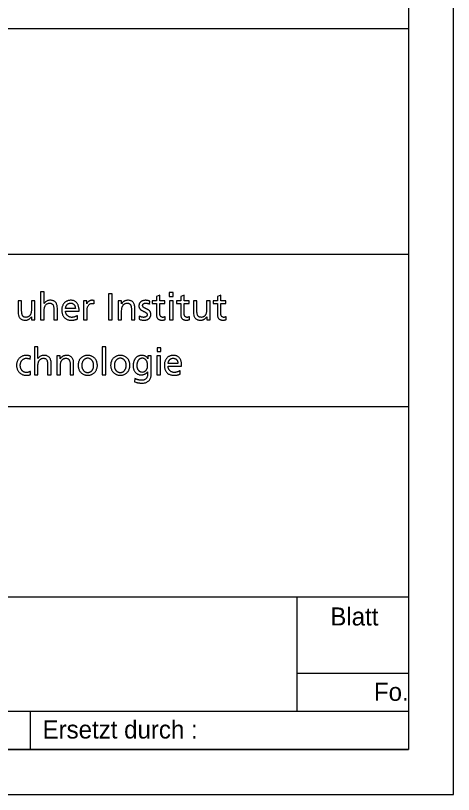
# Model space of a CAD drawing. Extents: x 0 to 841, y 0 to 594.
# Drawn here: x 792.3 to 841, y 0 to 86.5 of the extents above; entities that cross this region are included whole.
import ezdxf

# ---------------------------------------------------------------- set-up
doc = ezdxf.new("R2010")
doc.units = 0
doc.layers.add('90_Plankopf', color=7, linetype='Continuous')

msp = doc.modelspace()

# ---------------------------------------------------------------- linework, layer by layer
at = {"layer": '90_Plankopf'}
for p, q in [((836, 84.99), (658.12, 84.99)), ((836, 84.99), (836, 5)), ((658.12, 59.99), (836, 59.99)), ((658.12, 59.99), (836, 59.99)), ((836, 59.99), (836, 5)), ((801.057, 54.484), (801.057, 54.831)), ((807.232, 54.439), (807.265, 54.778)), ((798.972, 53.96), (797.883, 53.96)), ((797.883, 53.672), (799.385, 53.672)), ((799.224, 52.793), (799.224, 53.18)), ((806.072, 53.118), (806.052, 52.772)), ((808.962, 52.714), (808.962, 53.044)), ((811.666, 52.714), (811.666, 53.044)), ((815.744, 52.714), (815.744, 53.044)), ((793.951, 48.336), (793.984, 48.658)), ((810.373, 47.841), (809.283, 47.841)), ((794.001, 46.623), (793.972, 46.97)), ((809.283, 47.552), (810.785, 47.552)), ((810.624, 46.673), (810.624, 47.061)), ((805.596, 46.174), (805.555, 45.815)), ((752.001, 43.07), (836, 43.07)), ((752.001, 21.92), (836, 21.92)), ((823.647, 9.23), (823.647, 21.92)), ((823.647, 13.46), (836, 13.46)), ((752.001, 9.23), (836, 9.23)), ((794.001, 5), (794.001, 9.23)), ((836, 5), (658.12, 5)), ((669.8, 5), (836, 5)), ((669.8, 5), (836, 5))]:
    msp.add_line(p, q, dxfattribs=at)
for points in [[(0, 0), (841, 0), (841, 594), (0, 594)], [(25, 589), (836, 589), (836, 5), (25, 5)]]:
    msp.add_lwpolyline(points, close=True, dxfattribs=at)
for points in [[(795.509, 54.509), (795.501, 54.509), (795.501, 55.801), (795.113, 55.801), (795.113, 52.706), (795.501, 52.706), (795.501, 53.68)], [(802.646, 52.706), (803.059, 52.706), (803.059, 55.586), (802.646, 55.586), (802.646, 52.706)], [(808.371, 53.345), (808.371, 54.497), (808.929, 54.497), (808.929, 54.81), (808.371, 54.81), (808.371, 55.421), (807.984, 55.297), (807.984, 54.81), (807.509, 54.81), (807.509, 54.497), (807.984, 54.497), (807.984, 53.267)], [(809.853, 55.281), (809.853, 55.718), (809.416, 55.718), (809.416, 55.281), (809.853, 55.281)], [(811.075, 53.345), (811.075, 54.497), (811.633, 54.497), (811.633, 54.81), (811.075, 54.81), (811.075, 55.421), (810.688, 55.297), (810.688, 54.81), (810.213, 54.81), (810.213, 54.497), (810.688, 54.497), (810.688, 53.267)], [(815.154, 53.345), (815.154, 54.497), (815.711, 54.497), (815.711, 54.81), (815.154, 54.81), (815.154, 55.421), (814.766, 55.297), (814.766, 54.81), (814.291, 54.81), (814.291, 54.497), (814.766, 54.497), (814.766, 53.267)], [(793.004, 53.721), (793.004, 54.81), (792.616, 54.81), (792.616, 53.56)], [(794.093, 53.04), (794.102, 53.04), (794.102, 52.706), (794.477, 52.706), (794.477, 54.81), (794.089, 54.81), (794.089, 53.836)], [(800.252, 54.484), (800.244, 54.484), (800.244, 54.81), (799.881, 54.81), (799.881, 52.706), (800.269, 52.706), (800.269, 53.663)], [(804.116, 54.476), (804.108, 54.476), (804.108, 54.81), (803.732, 54.81), (803.732, 52.706), (804.12, 52.706), (804.12, 53.68)], [(809.441, 54.81), (809.441, 52.706), (809.829, 52.706), (809.829, 54.81), (809.441, 54.81)], [(812.483, 53.721), (812.483, 54.81), (812.095, 54.81), (812.095, 53.56)], [(813.573, 53.04), (813.581, 53.04), (813.581, 52.706), (813.956, 52.706), (813.956, 54.81), (813.568, 54.81), (813.568, 53.836)], [(796.587, 53.795), (796.587, 52.706), (796.974, 52.706), (796.974, 53.956)], [(805.205, 53.795), (805.205, 52.706), (805.593, 52.706), (805.593, 53.956)], [(794.818, 48.39), (794.81, 48.39), (794.81, 49.681), (794.422, 49.681), (794.422, 46.586), (794.81, 46.586), (794.81, 47.56)], [(801.963, 46.586), (802.351, 46.586), (802.351, 49.681), (801.963, 49.681), (801.963, 46.586)], [(808.493, 49.161), (808.493, 49.599), (808.056, 49.599), (808.056, 49.161), (808.493, 49.161)], [(797.303, 48.357), (797.295, 48.357), (797.295, 48.691), (796.919, 48.691), (796.919, 46.586), (797.307, 46.586), (797.307, 47.56)], [(807.395, 46.677), (807.395, 48.691), (807.036, 48.691), (807.036, 48.378), (807.028, 48.378)], [(808.031, 48.691), (808.031, 46.586), (808.419, 46.586), (808.419, 48.691), (808.031, 48.691)], [(795.895, 47.676), (795.895, 46.586), (796.283, 46.586), (796.283, 47.837)], [(798.393, 47.676), (798.393, 46.586), (798.78, 46.586), (798.78, 47.837)], [(806.999, 46.912), (807.007, 46.912), (807.007, 46.706)]]:
    msp.add_lwpolyline(points, dxfattribs=at)
for points in [[(795.501, 53.68), (795.501, 53.808), (795.514, 53.925), (795.539, 54.031), (795.565, 54.137), (795.603, 54.228), (795.655, 54.305), (795.708, 54.382), (795.774, 54.441), (795.855, 54.483), (795.935, 54.525), (796.031, 54.546), (796.141, 54.546), (796.253, 54.54), (796.342, 54.509), (796.407, 54.451), (796.473, 54.395), (796.519, 54.312), (796.546, 54.204), (796.574, 54.095), (796.587, 53.959), (796.587, 53.795)], [(796.974, 53.956), (796.975, 54.145), (796.947, 54.307), (796.891, 54.442), (796.836, 54.577), (796.749, 54.68), (796.633, 54.751), (796.516, 54.823), (796.368, 54.859), (796.186, 54.86), (796.038, 54.859), (795.907, 54.829), (795.791, 54.768), (795.675, 54.708), (795.581, 54.621), (795.509, 54.509)], [(799.385, 53.672), (799.386, 53.841), (799.37, 53.999), (799.339, 54.143), (799.307, 54.287), (799.256, 54.412), (799.184, 54.519), (799.112, 54.627), (799.017, 54.71), (798.898, 54.769), (798.779, 54.829), (798.631, 54.859), (798.457, 54.86), (798.307, 54.859), (798.173, 54.833), (798.051, 54.782), (797.931, 54.729), (797.827, 54.656), (797.741, 54.561), (797.654, 54.467), (797.587, 54.355), (797.541, 54.224), (797.494, 54.095), (797.471, 53.952), (797.47, 53.795), (797.47, 53.623), (797.492, 53.468), (797.536, 53.328), (797.579, 53.188), (797.646, 53.069), (797.735, 52.969), (797.825, 52.869), (797.937, 52.792), (798.074, 52.738), (798.212, 52.684), (798.373, 52.657), (798.56, 52.656), (798.675, 52.657), (798.772, 52.665), (798.853, 52.68), (798.934, 52.695), (799.004, 52.713), (799.063, 52.733), (799.122, 52.754), (799.175, 52.774), (799.224, 52.793)], [(797.883, 53.96), (797.89, 54.029), (797.906, 54.098), (797.93, 54.167), (797.954, 54.235), (797.989, 54.298), (798.034, 54.356), (798.079, 54.413), (798.135, 54.458), (798.204, 54.493), (798.272, 54.528), (798.353, 54.546), (798.448, 54.546), (798.532, 54.546), (798.606, 54.53), (798.671, 54.5), (798.737, 54.47), (798.791, 54.428), (798.836, 54.374), (798.88, 54.321), (798.915, 54.258), (798.937, 54.188), (798.961, 54.117), (798.972, 54.042), (798.972, 53.96)], [(801.057, 54.831), (801.03, 54.837), (801.004, 54.841), (800.98, 54.846), (800.955, 54.85), (800.928, 54.854), (800.9, 54.856), (800.872, 54.859), (800.839, 54.86), (800.801, 54.86), (800.726, 54.859), (800.653, 54.843), (800.582, 54.811), (800.512, 54.779), (800.448, 54.736), (800.391, 54.679), (800.333, 54.623), (800.287, 54.558), (800.252, 54.484)], [(800.269, 53.663), (800.269, 53.84), (800.293, 53.993), (800.34, 54.121), (800.388, 54.249), (800.454, 54.348), (800.54, 54.416), (800.625, 54.486), (800.726, 54.521), (800.842, 54.521), (800.876, 54.522), (800.911, 54.519), (800.948, 54.514), (800.985, 54.509), (801.021, 54.499), (801.057, 54.484)], [(805.593, 53.956), (805.594, 54.145), (805.566, 54.307), (805.51, 54.442), (805.454, 54.577), (805.368, 54.68), (805.251, 54.751), (805.135, 54.823), (804.986, 54.859), (804.805, 54.86), (804.707, 54.86), (804.612, 54.844), (804.522, 54.814), (804.431, 54.783), (804.351, 54.74), (804.281, 54.682), (804.21, 54.625), (804.155, 54.557), (804.116, 54.476)], [(804.12, 53.68), (804.12, 53.808), (804.132, 53.925), (804.158, 54.031), (804.183, 54.137), (804.222, 54.228), (804.274, 54.305), (804.326, 54.382), (804.393, 54.441), (804.473, 54.483), (804.554, 54.525), (804.65, 54.546), (804.76, 54.546), (804.872, 54.54), (804.96, 54.509), (805.026, 54.451), (805.091, 54.395), (805.137, 54.312), (805.165, 54.204), (805.193, 54.095), (805.206, 53.959), (805.205, 53.795)], [(807.265, 54.778), (807.189, 54.801), (807.112, 54.82), (807.035, 54.836), (806.956, 54.851), (806.872, 54.859), (806.782, 54.86), (806.678, 54.86), (806.58, 54.847), (806.491, 54.82), (806.401, 54.794), (806.322, 54.753), (806.255, 54.7), (806.187, 54.647), (806.134, 54.579), (806.097, 54.498), (806.059, 54.417), (806.04, 54.321), (806.039, 54.212), (806.04, 54.128), (806.057, 54.056), (806.09, 53.994), (806.123, 53.933), (806.166, 53.88), (806.22, 53.834), (806.275, 53.79), (806.334, 53.75), (806.398, 53.715), (806.463, 53.68), (806.528, 53.647), (806.593, 53.617), (806.657, 53.586), (806.717, 53.555), (806.77, 53.522), (806.825, 53.49), (806.868, 53.454), (806.901, 53.413), (806.933, 53.373), (806.951, 53.325), (806.951, 53.271), (806.951, 53.215), (806.938, 53.167), (806.914, 53.128), (806.891, 53.09), (806.859, 53.059), (806.82, 53.035), (806.781, 53.012), (806.738, 52.995), (806.692, 52.985), (806.646, 52.975), (806.6, 52.97), (806.555, 52.97), (806.517, 52.97), (806.47, 52.975), (806.414, 52.986), (806.359, 52.997), (806.301, 53.014), (806.241, 53.036), (806.18, 53.058), (806.125, 53.085), (806.072, 53.118)], [(806.052, 52.772), (806.141, 52.726), (806.235, 52.694), (806.333, 52.678), (806.431, 52.662), (806.53, 52.655), (806.63, 52.656), (806.725, 52.656), (806.815, 52.669), (806.902, 52.695), (806.99, 52.722), (807.068, 52.762), (807.138, 52.816), (807.207, 52.869), (807.262, 52.938), (807.302, 53.02), (807.343, 53.103), (807.363, 53.2), (807.364, 53.312), (807.363, 53.408), (807.346, 53.489), (807.314, 53.556), (807.281, 53.622), (807.237, 53.679), (807.183, 53.726), (807.129, 53.772), (807.07, 53.811), (807.005, 53.845), (806.94, 53.878), (806.876, 53.909), (806.811, 53.937), (806.746, 53.966), (806.687, 53.995), (806.633, 54.026), (806.579, 54.058), (806.535, 54.095), (806.502, 54.136), (806.47, 54.179), (806.453, 54.23), (806.452, 54.291), (806.453, 54.348), (806.471, 54.396), (806.504, 54.434), (806.538, 54.472), (806.583, 54.5), (806.639, 54.519), (806.695, 54.538), (806.757, 54.546), (806.823, 54.546), (806.847, 54.546), (806.877, 54.543), (806.914, 54.538), (806.95, 54.531), (806.989, 54.523), (807.029, 54.513), (807.07, 54.503), (807.108, 54.491), (807.145, 54.478), (807.18, 54.466), (807.209, 54.453), (807.232, 54.439)], [(794.089, 53.836), (794.089, 53.708), (794.077, 53.591), (794.051, 53.485), (794.026, 53.379), (793.988, 53.288), (793.935, 53.211), (793.883, 53.134), (793.816, 53.075), (793.736, 53.033), (793.655, 52.991), (793.56, 52.97), (793.45, 52.97), (793.338, 52.977), (793.249, 53.008), (793.184, 53.065), (793.118, 53.121), (793.072, 53.204), (793.045, 53.312), (793.016, 53.421), (793.003, 53.557), (793.004, 53.721)], [(799.224, 53.18), (799.2, 53.16), (799.165, 53.138), (799.119, 53.114), (799.073, 53.09), (799.021, 53.068), (798.961, 53.045), (798.901, 53.023), (798.838, 53.006), (798.772, 52.992), (798.706, 52.978), (798.641, 52.97), (798.576, 52.97), (798.483, 52.97), (798.396, 52.987), (798.313, 53.021), (798.23, 53.054), (798.156, 53.103), (798.092, 53.165), (798.027, 53.227), (797.976, 53.3), (797.939, 53.386), (797.903, 53.472), (797.884, 53.567), (797.883, 53.672)], [(813.568, 53.836), (813.568, 53.708), (813.556, 53.591), (813.531, 53.485), (813.505, 53.379), (813.467, 53.288), (813.414, 53.211), (813.362, 53.134), (813.295, 53.075), (813.215, 53.033), (813.135, 52.991), (813.039, 52.97), (812.929, 52.97), (812.817, 52.977), (812.728, 53.008), (812.663, 53.065), (812.597, 53.121), (812.551, 53.204), (812.524, 53.312), (812.495, 53.421), (812.483, 53.557), (812.483, 53.721)], [(792.616, 53.56), (792.616, 53.371), (792.644, 53.209), (792.699, 53.074), (792.755, 52.939), (792.842, 52.836), (792.958, 52.765), (793.074, 52.693), (793.224, 52.657), (793.404, 52.656), (793.503, 52.657), (793.598, 52.672), (793.688, 52.702), (793.778, 52.733), (793.858, 52.777), (793.929, 52.834), (793.999, 52.891), (794.054, 52.96), (794.093, 53.04)], [(807.984, 53.267), (807.984, 53.127), (808.01, 53.012), (808.063, 52.922), (808.115, 52.832), (808.189, 52.764), (808.285, 52.721), (808.383, 52.678), (808.497, 52.656), (808.631, 52.656), (808.694, 52.657), (808.754, 52.664), (808.81, 52.676), (808.867, 52.688), (808.918, 52.701), (808.962, 52.714)], [(808.962, 53.044), (808.933, 53.025), (808.896, 53.008), (808.853, 52.993), (808.809, 52.978), (808.757, 52.97), (808.698, 52.97), (808.638, 52.97), (808.583, 52.984), (808.534, 53.013), (808.485, 53.042), (808.446, 53.084), (808.417, 53.14), (808.387, 53.196), (808.372, 53.264), (808.371, 53.345)], [(810.688, 53.267), (810.688, 53.127), (810.714, 53.012), (810.767, 52.922), (810.819, 52.832), (810.893, 52.764), (810.989, 52.721), (811.087, 52.678), (811.201, 52.656), (811.335, 52.656), (811.398, 52.657), (811.458, 52.664), (811.514, 52.676), (811.571, 52.688), (811.622, 52.701), (811.666, 52.714)], [(811.666, 53.044), (811.637, 53.025), (811.6, 53.008), (811.557, 52.993), (811.513, 52.978), (811.461, 52.97), (811.401, 52.97), (811.342, 52.97), (811.287, 52.984), (811.238, 53.013), (811.189, 53.042), (811.15, 53.084), (811.121, 53.14), (811.091, 53.196), (811.076, 53.264), (811.075, 53.345)], [(812.095, 53.56), (812.095, 53.371), (812.123, 53.209), (812.178, 53.074), (812.234, 52.939), (812.321, 52.836), (812.437, 52.765), (812.553, 52.693), (812.702, 52.657), (812.883, 52.656), (812.982, 52.657), (813.077, 52.672), (813.167, 52.702), (813.257, 52.733), (813.337, 52.777), (813.408, 52.834), (813.478, 52.891), (813.533, 52.96), (813.573, 53.04)], [(814.766, 53.267), (814.766, 53.127), (814.793, 53.012), (814.845, 52.922), (814.897, 52.832), (814.971, 52.764), (815.068, 52.721), (815.165, 52.678), (815.28, 52.656), (815.414, 52.656), (815.476, 52.657), (815.536, 52.664), (815.592, 52.676), (815.65, 52.688), (815.7, 52.701), (815.744, 52.714)], [(815.744, 53.044), (815.715, 53.025), (815.678, 53.008), (815.635, 52.993), (815.591, 52.978), (815.539, 52.97), (815.48, 52.97), (815.42, 52.97), (815.365, 52.984), (815.316, 53.013), (815.267, 53.042), (815.228, 53.084), (815.199, 53.14), (815.169, 53.196), (815.154, 53.264), (815.154, 53.345)], [(793.984, 48.658), (793.946, 48.673), (793.901, 48.687), (793.848, 48.7), (793.795, 48.712), (793.739, 48.722), (793.681, 48.729), (793.622, 48.737), (793.567, 48.74), (793.514, 48.74), (793.352, 48.74), (793.206, 48.712), (793.074, 48.659), (792.943, 48.605), (792.83, 48.528), (792.736, 48.43), (792.642, 48.331), (792.569, 48.215), (792.518, 48.081), (792.467, 47.947), (792.442, 47.8), (792.441, 47.639), (792.442, 47.488), (792.468, 47.345), (792.519, 47.212), (792.571, 47.079), (792.644, 46.963), (792.739, 46.862), (792.834, 46.761), (792.947, 46.681), (793.078, 46.624), (793.209, 46.567), (793.354, 46.538), (793.514, 46.537), (793.561, 46.537), (793.612, 46.539), (793.667, 46.543), (793.722, 46.547), (793.777, 46.555), (793.834, 46.568), (793.891, 46.581), (793.946, 46.599), (794.001, 46.623)], [(793.972, 46.97), (793.932, 46.944), (793.887, 46.922), (793.84, 46.904), (793.793, 46.886), (793.744, 46.873), (793.695, 46.864), (793.647, 46.855), (793.6, 46.85), (793.555, 46.85), (793.456, 46.851), (793.367, 46.866), (793.29, 46.897), (793.214, 46.926), (793.148, 46.967), (793.092, 47.02), (793.037, 47.072), (792.992, 47.132), (792.957, 47.199), (792.921, 47.267), (792.896, 47.337), (792.878, 47.412), (792.862, 47.488), (792.854, 47.563), (792.854, 47.639), (792.854, 47.74), (792.868, 47.838), (792.898, 47.931), (792.928, 48.025), (792.972, 48.109), (793.03, 48.183), (793.087, 48.258), (793.157, 48.317), (793.241, 48.36), (793.325, 48.403), (793.422, 48.426), (793.53, 48.427), (793.593, 48.427), (793.66, 48.42), (793.731, 48.405), (793.803, 48.39), (793.876, 48.367), (793.951, 48.336)], [(794.81, 47.56), (794.81, 47.689), (794.823, 47.806), (794.848, 47.912), (794.873, 48.018), (794.912, 48.109), (794.964, 48.185), (795.016, 48.263), (795.083, 48.322), (795.164, 48.364), (795.244, 48.406), (795.34, 48.426), (795.45, 48.427), (795.562, 48.42), (795.651, 48.389), (795.716, 48.332), (795.781, 48.276), (795.827, 48.193), (795.855, 48.084), (795.883, 47.976), (795.896, 47.84), (795.895, 47.676)], [(796.283, 47.837), (796.284, 48.026), (796.256, 48.188), (796.2, 48.323), (796.144, 48.457), (796.058, 48.56), (795.942, 48.632), (795.825, 48.704), (795.677, 48.74), (795.495, 48.74), (795.347, 48.74), (795.216, 48.709), (795.1, 48.649), (794.983, 48.589), (794.89, 48.502), (794.818, 48.39)], [(798.78, 47.837), (798.781, 48.026), (798.753, 48.188), (798.697, 48.323), (798.642, 48.457), (798.555, 48.56), (798.439, 48.632), (798.323, 48.704), (798.174, 48.74), (797.992, 48.74), (797.894, 48.74), (797.799, 48.725), (797.709, 48.695), (797.619, 48.664), (797.538, 48.62), (797.468, 48.562), (797.398, 48.505), (797.342, 48.437), (797.303, 48.357)], [(797.307, 47.56), (797.307, 47.689), (797.32, 47.806), (797.345, 47.912), (797.371, 48.018), (797.409, 48.109), (797.461, 48.185), (797.514, 48.263), (797.58, 48.322), (797.661, 48.364), (797.741, 48.406), (797.837, 48.426), (797.947, 48.427), (798.059, 48.42), (798.148, 48.389), (798.213, 48.332), (798.278, 48.276), (798.325, 48.193), (798.352, 48.084), (798.38, 47.976), (798.393, 47.84), (798.393, 47.676)], [(801.395, 47.891), (801.382, 47.957), (801.364, 48.02), (801.341, 48.081), (801.29, 48.215), (801.218, 48.331), (801.124, 48.43), (801.029, 48.528), (800.917, 48.605), (800.786, 48.659), (800.655, 48.712), (800.51, 48.74), (800.349, 48.74), (800.188, 48.74), (800.041, 48.712), (799.91, 48.659), (799.778, 48.605), (799.666, 48.528), (799.571, 48.43), (799.477, 48.331), (799.404, 48.215), (799.353, 48.081), (799.302, 47.947), (799.277, 47.8), (799.276, 47.639)], [(799.689, 47.639), (799.689, 47.74), (799.704, 47.838), (799.734, 47.931), (799.763, 48.025), (799.806, 48.109), (799.863, 48.183), (799.919, 48.258), (799.989, 48.317), (800.07, 48.36), (800.152, 48.403), (800.245, 48.426), (800.349, 48.427), (800.452, 48.426), (800.544, 48.403), (800.626, 48.36), (800.707, 48.317), (800.776, 48.258), (800.832, 48.183), (800.888, 48.109), (800.932, 48.025), (800.961, 47.931), (800.99, 47.838), (801.005, 47.74), (801.005, 47.639), (801.005, 47.563), (800.997, 47.488), (800.981, 47.412), (800.964, 47.337), (800.939, 47.267), (800.905, 47.199), (800.871, 47.132), (800.829, 47.072), (800.776, 47.02), (800.724, 46.967), (800.663, 46.926), (800.592, 46.897), (800.521, 46.866), (800.44, 46.851), (800.349, 46.85), (800.258, 46.851), (800.176, 46.866), (800.104, 46.897), (800.033, 46.926), (799.971, 46.967), (799.919, 47.02), (799.866, 47.072), (799.824, 47.132), (799.79, 47.199), (799.756, 47.267), (799.73, 47.337), (799.714, 47.412), (799.697, 47.488), (799.689, 47.563), (799.689, 47.639)], [(805.015, 47.891), (805.002, 47.957), (804.984, 48.02), (804.961, 48.081), (804.91, 48.215), (804.838, 48.331), (804.744, 48.43), (804.65, 48.528), (804.537, 48.605), (804.406, 48.659), (804.275, 48.712), (804.13, 48.74), (803.97, 48.74), (803.808, 48.74), (803.661, 48.712), (803.53, 48.659), (803.399, 48.605), (803.286, 48.528), (803.192, 48.43), (803.097, 48.331), (803.024, 48.215), (802.973, 48.081), (802.923, 47.947), (802.897, 47.8), (802.897, 47.639)], [(803.309, 47.639), (803.309, 47.74), (803.324, 47.838), (803.354, 47.931), (803.383, 48.025), (803.426, 48.109), (803.483, 48.183), (803.54, 48.258), (803.609, 48.317), (803.69, 48.36), (803.772, 48.403), (803.865, 48.426), (803.97, 48.427), (804.073, 48.426), (804.165, 48.403), (804.246, 48.36), (804.327, 48.317), (804.396, 48.258), (804.452, 48.183), (804.509, 48.109), (804.552, 48.025), (804.581, 47.931), (804.611, 47.838), (804.625, 47.74), (804.625, 47.639), (804.625, 47.563), (804.617, 47.488), (804.601, 47.412), (804.584, 47.337), (804.56, 47.267), (804.525, 47.199), (804.492, 47.132), (804.449, 47.072), (804.396, 47.02), (804.345, 46.967), (804.283, 46.926), (804.212, 46.897), (804.141, 46.866), (804.06, 46.851), (803.97, 46.85), (803.878, 46.851), (803.796, 46.866), (803.725, 46.897), (803.653, 46.926), (803.591, 46.967), (803.539, 47.02), (803.487, 47.072), (803.444, 47.132), (803.41, 47.199), (803.376, 47.267), (803.351, 47.337), (803.334, 47.412), (803.317, 47.488), (803.309, 47.563), (803.309, 47.639)], [(807.028, 48.378), (806.99, 48.454), (806.941, 48.518), (806.879, 48.573), (806.818, 48.626), (806.743, 48.668), (806.654, 48.697), (806.564, 48.726), (806.457, 48.74), (806.334, 48.74), (806.207, 48.74), (806.094, 48.718), (805.993, 48.676), (805.892, 48.634), (805.804, 48.576), (805.729, 48.502), (805.653, 48.429), (805.592, 48.344), (805.542, 48.25), (805.492, 48.155), (805.455, 48.053), (805.431, 47.946), (805.406, 47.839), (805.394, 47.731), (805.394, 47.622), (805.394, 47.485), (805.412, 47.355), (805.45, 47.231), (805.487, 47.107), (805.543, 46.996), (805.618, 46.9), (805.692, 46.804), (805.786, 46.727), (805.899, 46.672), (806.011, 46.616), (806.143, 46.588), (806.294, 46.586), (806.383, 46.586), (806.472, 46.598), (806.559, 46.622), (806.646, 46.646), (806.727, 46.683), (806.802, 46.731), (806.878, 46.779), (806.943, 46.84), (806.999, 46.912)], [(806.392, 46.9), (806.302, 46.901), (806.22, 46.921), (806.148, 46.961), (806.075, 47), (806.014, 47.054), (805.963, 47.123), (805.912, 47.192), (805.874, 47.271), (805.847, 47.359), (805.82, 47.449), (805.806, 47.543), (805.806, 47.643), (805.806, 47.715), (805.814, 47.788), (805.83, 47.862), (805.845, 47.936), (805.868, 48.007), (805.9, 48.074), (805.931, 48.141), (805.97, 48.201), (806.017, 48.254), (806.064, 48.307), (806.119, 48.349), (806.181, 48.38), (806.244, 48.41), (806.314, 48.426), (806.392, 48.427), (806.496, 48.426), (806.586, 48.404), (806.663, 48.362), (806.74, 48.319), (806.804, 48.26), (806.855, 48.185), (806.905, 48.109), (806.944, 48.023), (806.969, 47.925), (806.995, 47.828), (807.007, 47.724), (807.007, 47.614), (807.007, 47.516), (806.992, 47.423), (806.963, 47.337), (806.933, 47.251), (806.89, 47.175), (806.836, 47.11), (806.782, 47.045), (806.717, 46.994), (806.642, 46.956), (806.566, 46.919), (806.484, 46.901), (806.392, 46.9)], [(810.785, 47.552), (810.786, 47.722), (810.77, 47.88), (810.739, 48.023), (810.708, 48.168), (810.656, 48.293), (810.585, 48.4), (810.512, 48.507), (810.417, 48.591), (810.298, 48.65), (810.179, 48.709), (810.032, 48.74), (809.857, 48.74), (809.708, 48.74), (809.573, 48.714), (809.452, 48.662), (809.331, 48.61), (809.227, 48.537), (809.141, 48.442), (809.054, 48.347), (808.987, 48.235), (808.941, 48.105), (808.895, 47.976), (808.871, 47.833), (808.871, 47.676), (808.871, 47.504), (808.892, 47.348), (808.936, 47.209), (808.979, 47.069), (809.046, 46.95), (809.135, 46.85), (809.225, 46.749), (809.338, 46.672), (809.474, 46.619), (809.612, 46.564), (809.774, 46.538), (809.96, 46.537), (810.075, 46.538), (810.172, 46.545), (810.254, 46.56), (810.334, 46.575), (810.404, 46.593), (810.464, 46.614), (810.522, 46.634), (810.576, 46.654), (810.624, 46.673)], [(809.283, 47.841), (809.29, 47.91), (809.306, 47.978), (809.331, 48.047), (809.355, 48.116), (809.389, 48.179), (809.434, 48.236), (809.479, 48.294), (809.536, 48.339), (809.604, 48.374), (809.672, 48.408), (809.754, 48.426), (809.849, 48.427), (809.932, 48.426), (810.007, 48.411), (810.071, 48.381), (810.137, 48.35), (810.191, 48.309), (810.236, 48.255), (810.28, 48.201), (810.315, 48.139), (810.338, 48.069), (810.361, 47.998), (810.373, 47.922), (810.373, 47.841)], [(799.276, 47.639), (799.277, 47.488), (799.303, 47.345), (799.355, 47.212), (799.406, 47.079), (799.479, 46.963), (799.575, 46.862), (799.67, 46.761), (799.782, 46.681), (799.913, 46.624), (800.045, 46.567), (800.19, 46.538), (800.349, 46.537), (800.507, 46.538), (800.653, 46.567), (800.782, 46.624), (800.913, 46.681), (801.026, 46.761), (801.12, 46.862), (801.215, 46.963), (801.288, 47.079), (801.34, 47.212), (801.391, 47.345), (801.417, 47.488), (801.418, 47.639), (801.418, 47.727), (801.41, 47.811), (801.395, 47.891)], [(802.897, 47.639), (802.897, 47.488), (802.923, 47.345), (802.975, 47.212), (803.026, 47.079), (803.099, 46.963), (803.195, 46.862), (803.29, 46.761), (803.403, 46.681), (803.533, 46.624), (803.665, 46.567), (803.81, 46.538), (803.97, 46.537), (804.128, 46.538), (804.273, 46.567), (804.403, 46.624), (804.533, 46.681), (804.646, 46.761), (804.74, 46.862), (804.835, 46.963), (804.908, 47.079), (804.96, 47.212), (805.012, 47.345), (805.037, 47.488), (805.038, 47.639), (805.038, 47.727), (805.03, 47.811), (805.015, 47.891)], [(807.007, 46.706), (807.006, 46.557), (806.981, 46.428), (806.929, 46.321), (806.877, 46.213), (806.803, 46.13), (806.706, 46.072), (806.609, 46.014), (806.492, 45.984), (806.355, 45.984), (806.284, 45.984), (806.219, 45.987), (806.158, 45.994), (806.097, 46.001), (806.038, 46.013), (805.98, 46.028), (805.922, 46.043), (805.862, 46.062), (805.8, 46.086), (805.737, 46.11), (805.67, 46.14), (805.596, 46.174)], [(810.624, 47.061), (810.6, 47.041), (810.565, 47.019), (810.519, 46.995), (810.473, 46.971), (810.421, 46.948), (810.361, 46.926), (810.301, 46.904), (810.238, 46.886), (810.172, 46.872), (810.106, 46.858), (810.041, 46.851), (809.976, 46.85), (809.884, 46.851), (809.796, 46.868), (809.713, 46.902), (809.631, 46.935), (809.556, 46.983), (809.492, 47.045), (809.428, 47.107), (809.377, 47.181), (809.34, 47.267), (809.303, 47.353), (809.284, 47.448), (809.283, 47.552)], [(805.555, 45.815), (805.666, 45.777), (805.765, 45.746), (805.851, 45.726), (805.937, 45.704), (806.017, 45.69), (806.09, 45.682), (806.163, 45.673), (806.237, 45.67), (806.31, 45.67), (806.561, 45.671), (806.767, 45.71), (806.927, 45.789), (807.087, 45.868), (807.205, 45.982), (807.282, 46.132), (807.358, 46.282), (807.396, 46.463), (807.395, 46.677)]]:
    msp.add_open_spline(points, degree=3, dxfattribs=at)

# ---------------------------------------------------------------- texts
for s, p in [('Blatt', (827.314, 18.758)), ('Fo.', (832.16, 10.392)), ('Ersetzt durch :', (795.327, 6.209))]:
    msp.add_text(s, height=2, dxfattribs=at).set_placement(p)

doc.saveas('drawing.dxf')
